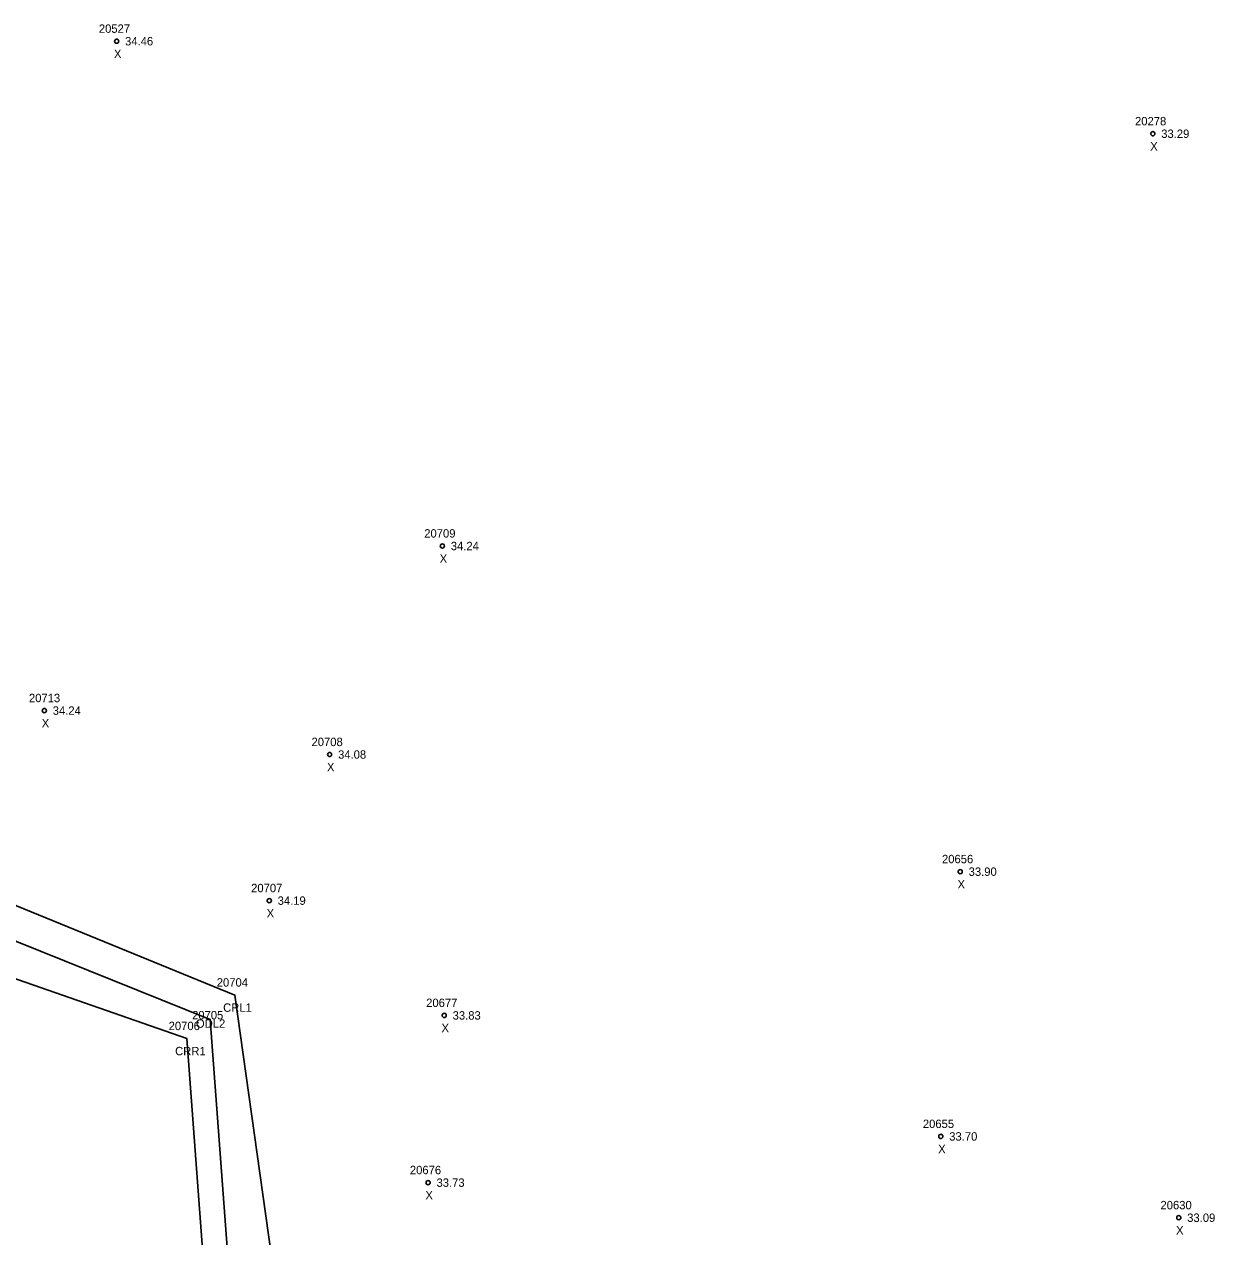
# Model space of a CAD drawing. Extents: x 2445178 to 2446260, y 791158 to 792318.
# Drawn here: x 2445430.8 to 2445572.5, y 791780.8 to 791925.1 of the extents above; entities that cross this region are included whole.
import ezdxf

# ---------------------------------------------------------------- set-up
doc = ezdxf.new("R2010")
doc.units = 0
for name, color, linetype in [('RD_EX_H2O', 7, 'Continuous'), ('RD_EX_H2O_txCode', 7, 'Continuous'), ('RD_Sketch8', 7, 'Continuous'), ('RD_SMD_Locator', 7, 'Continuous')]:
    doc.layers.add(name, color=color, linetype=linetype)

msp = doc.modelspace()

# ---------------------------------------------------------------- linework, layer by layer
at = {"layer": 'RD_EX_H2O'}
for points in [[(2445544.99, 791749.08), (2445517.8, 791768.36), (2445478.59, 791760.86), (2445463.48, 791763.9), (2445460.87, 791773.93), (2445455.89, 791809.54), (2445415.21, 791826.15)], [(2445536.09, 791752.19), (2445517.24, 791765.41), (2445479.3, 791757.52), (2445462.61, 791759.06), (2445455.58, 791771.48), (2445452.95, 791806.64), (2445409.65, 791824.04)], [(2445530.12, 791747.41), (2445515.88, 791756.64), (2445479.19, 791754.53), (2445461.81, 791756.69), (2445452.6, 791771.81), (2445450.18, 791804.36), (2445403.09, 791820.76)]]:
    msp.add_lwpolyline(points, dxfattribs=at)
at = {"layer": 'RD_SMD_Locator'}
for centre, radius in [((2445441.81, 791923.12), 0.25), ((2445565.17, 791912.1), 0.25), ((2445480.59, 791863.01), 0.25), ((2445433.2, 791843.41), 0.25), ((2445467.17, 791838.18), 0.25), ((2445542.24, 791824.23), 0.25), ((2445459.98, 791820.78), 0.25), ((2445455.89, 791809.54), 0.001), ((2445452.95, 791806.64), 0.001), ((2445480.81, 791807.11), 0.25), ((2445450.18, 791804.36), 0.001), ((2445539.93, 791792.7), 0.25), ((2445478.89, 791787.2), 0.25), ((2445568.26, 791783.02), 0.25)]:
    msp.add_circle(centre, radius, dxfattribs=at)

# ---------------------------------------------------------------- texts
at = {"layer": 'RD_EX_H2O_txCode'}
for s, p in [('20704', (2445453.73, 791810.54)), ('CRL1', (2445454.49, 791807.54)), ('20705', (2445450.79, 791806.64)), ('ODL2', (2445451.25, 791805.64)), ('20706', (2445448, 791805.36)), ('CRR1', (2445448.77, 791802.36))]:
    msp.add_text(s, height=1, dxfattribs=at).set_placement(p)
at = {"layer": 'RD_Sketch8'}
for s, p in [('20527', (2445439.69, 791924.12)), ('34.46', (2445442.81, 791922.62)), ('X', (2445441.49, 791921.12)), ('20278', (2445563.05, 791913.1)), ('33.29', (2445566.17, 791911.6)), ('X', (2445564.86, 791910.1)), ('20709', (2445478.43, 791864.01)), ('34.24', (2445481.59, 791862.51)), ('X', (2445480.27, 791861.01)), ('20713', (2445431.37, 791844.41)), ('34.24', (2445434.2, 791842.91)), ('X', (2445432.89, 791841.41)), ('20708', (2445465.01, 791839.18)), ('34.08', (2445468.17, 791837.68)), ('X', (2445466.85, 791836.18)), ('20656', (2445540.07, 791825.23)), ('33.90', (2445543.24, 791823.73)), ('20707', (2445457.82, 791821.78)), ('X', (2445541.92, 791822.23)), ('34.19', (2445460.98, 791820.28)), ('X', (2445459.67, 791818.78)), ('20677', (2445478.66, 791808.11)), ('33.83', (2445481.81, 791806.61)), ('X', (2445480.49, 791805.11)), ('20655', (2445537.79, 791793.7)), ('33.70', (2445540.93, 791792.2)), ('X', (2445539.61, 791790.7)), ('20676', (2445476.72, 791788.2)), ('33.73', (2445479.89, 791786.7)), ('X', (2445478.57, 791785.2)), ('20630', (2445566.08, 791784.02)), ('33.09', (2445569.26, 791782.52)), ('X', (2445567.94, 791781.02))]:
    msp.add_text(s, height=1, dxfattribs=at).set_placement(p)

doc.saveas('drawing.dxf')
